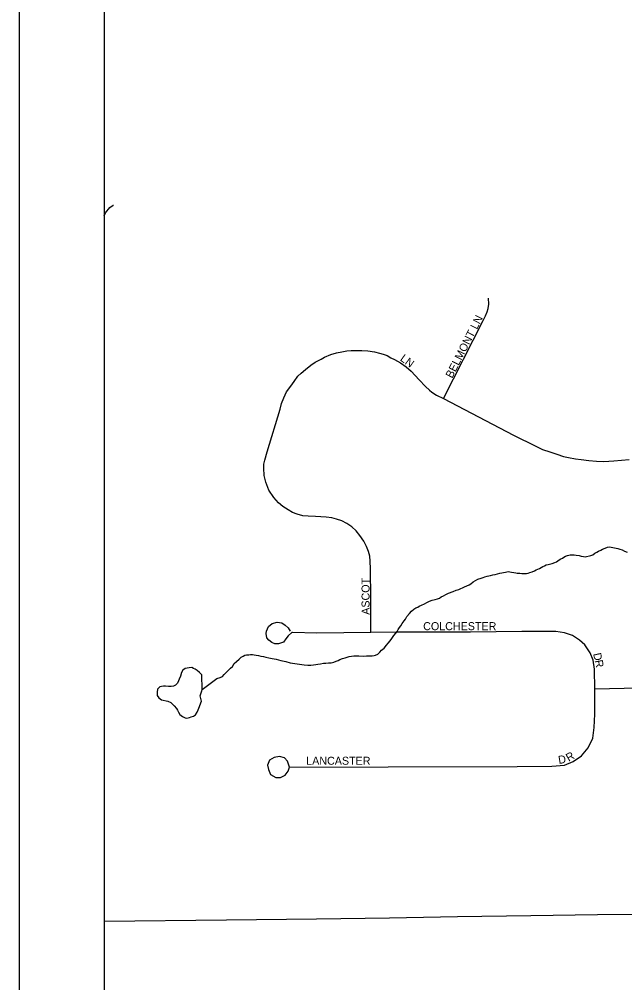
# Model space of a CAD drawing. Extents: x 0 to 34, y 0 to 22.
# Drawn here: x 2.262 to 2.978, y 16.919 to 18.059 of the extents above; entities that cross this region are included whole.
import ezdxf

# ---------------------------------------------------------------- set-up
doc = ezdxf.new("R2010")
doc.units = 0
for name, color, linetype in [('GM_X_County', 7, 'Continuous'), ('GM_X_County_Road', 7, 'Continuous'), ('GM_X_Minor_Lake', 7, 'Continuous'), ('GM_X_Minor_River', 7, 'Continuous'), ('GM_X_Township', 7, 'Continuous'), ('GM_X_Township_Subdivision', 7, 'Continuous'), ('GM_X_Township_Subdivision_Text', 7, 'Continuous'), ('SH_Data', 7, 'Continuous')]:
    doc.layers.add(name, color=color, linetype=linetype)

msp = doc.modelspace()

# ---------------------------------------------------------------- linework, layer by layer
at = {"layer": 'GM_X_County'}
msp.add_lwpolyline([(9.1622, 14.342), (9.1622, 21.1385), (2.3622, 21.1385), (2.3622, 14.3385), (9.0003, 14.3385)], dxfattribs=at)
at = {"layer": 'GM_X_County_Road'}
msp.add_lwpolyline([(2.3622, 16.9922), (2.5068, 16.9937), (2.6134, 16.9952), (2.6997, 16.9964), (2.7801, 16.9979), (2.8667, 16.9989), (2.9456, 17.0001), (3.0383, 17.0011), (3.101, 17.0021), (3.1135, 17.0021)], dxfattribs=at)
at = {"layer": 'GM_X_Minor_Lake'}
for points in [[(2.4775, 17.2835), (2.4747, 17.2865), (2.472, 17.2887), (2.4697, 17.2902), (2.4678, 17.2913), (2.4659, 17.2924), (2.4628, 17.292), (2.4579, 17.2911), (2.4553, 17.2891), (2.4534, 17.2864), (2.4524, 17.2822), (2.451, 17.2784), (2.4499, 17.2765), (2.4488, 17.2738), (2.4465, 17.2715), (2.4443, 17.2703), (2.4412, 17.2698), (2.4382, 17.2698), (2.4348, 17.2701), (2.4325, 17.2704), (2.4298, 17.27), (2.4279, 17.2695), (2.4253, 17.2668), (2.4247, 17.263), (2.4247, 17.2592), (2.4267, 17.2566), (2.4298, 17.254)], [(2.4775, 17.2835), (2.4747, 17.2865), (2.472, 17.2887), (2.4697, 17.2902), (2.4678, 17.2913), (2.4659, 17.2924), (2.4628, 17.292), (2.4579, 17.2911), (2.4553, 17.2891), (2.4534, 17.2864), (2.4524, 17.2822), (2.451, 17.2784), (2.4499, 17.2765), (2.4488, 17.2738), (2.4465, 17.2715), (2.4443, 17.2703), (2.4412, 17.2698), (2.4382, 17.2698), (2.4348, 17.2701), (2.4325, 17.2704), (2.4298, 17.27), (2.4279, 17.2695), (2.4253, 17.2668), (2.4247, 17.263), (2.4247, 17.2592), (2.4267, 17.2566), (2.4298, 17.254), (2.4374, 17.2526), (2.4409, 17.2508), (2.4428, 17.249), (2.4448, 17.2471), (2.4475, 17.2437), (2.4487, 17.2419), (2.4499, 17.2396), (2.4518, 17.2366), (2.4549, 17.2344), (2.458, 17.2329), (2.4599, 17.2326), (2.463, 17.233), (2.4652, 17.2339), (2.4679, 17.2347), (2.4701, 17.2362), (2.4723, 17.2397), (2.4734, 17.2424), (2.4748, 17.2462), (2.4763, 17.2504), (2.4774, 17.2524), (2.4765, 17.2558), (2.4757, 17.2588), (2.4764, 17.2611), (2.4775, 17.2649), (2.4782, 17.2664), (2.4775, 17.2835)], [(2.4298, 17.254), (2.4374, 17.2526), (2.4409, 17.2508), (2.4428, 17.249), (2.4448, 17.2471), (2.4475, 17.2437), (2.4487, 17.2419), (2.4499, 17.2396), (2.4518, 17.2366), (2.4549, 17.2344), (2.458, 17.2329), (2.4599, 17.2326), (2.463, 17.233), (2.4652, 17.2339), (2.4679, 17.2347), (2.4701, 17.2362), (2.4723, 17.2397), (2.4734, 17.2424), (2.4748, 17.2462), (2.4763, 17.2504), (2.4774, 17.2524), (2.4765, 17.2558), (2.4757, 17.2588), (2.4764, 17.2611), (2.4775, 17.2649), (2.4782, 17.2664), (2.4775, 17.2835)]]:
    msp.add_lwpolyline(points, dxfattribs=at)
at = {"layer": 'GM_X_Minor_River'}
for points in [[(2.3622, 17.8265), (2.3639, 17.8302), (2.3687, 17.8364), (2.3728, 17.8391), (2.3732, 17.8392)], [(2.7785, 17.3839), (2.7815, 17.3848), (2.7838, 17.3856), (2.7861, 17.3864), (2.7883, 17.3876), (2.791, 17.3888), (2.7936, 17.39), (2.7959, 17.3915), (2.7985, 17.3935), (2.8011, 17.3951), (2.8041, 17.3967), (2.8079, 17.3979), (2.8102, 17.3987), (2.8124, 17.3995), (2.8151, 17.4003), (2.817, 17.4007), (2.8189, 17.4012), (2.8219, 17.402), (2.8245, 17.4024), (2.8302, 17.4041), (2.8325, 17.4045), (2.8344, 17.4049), (2.8366, 17.4053), (2.8401, 17.4058), (2.842, 17.4055), (2.8439, 17.4051), (2.8465, 17.4048), (2.8488, 17.4045), (2.8507, 17.4041), (2.8538, 17.4038), (2.8561, 17.4035), (2.8587, 17.4035), (2.8614, 17.4036), (2.8637, 17.404), (2.8656, 17.4048), (2.8682, 17.4056), (2.8709, 17.4065), (2.8731, 17.4077), (2.8769, 17.4096), (2.8791, 17.4108), (2.881, 17.412), (2.8829, 17.4128), (2.8848, 17.4136), (2.8871, 17.414), (2.8889, 17.4145), (2.892, 17.4153), (2.895, 17.4165), (2.8969, 17.4173), (2.9002, 17.4196), (2.9021, 17.4208), (2.904, 17.4216), (2.9059, 17.4228), (2.9078, 17.424), (2.91, 17.4248), (2.9134, 17.4256), (2.9157, 17.4257), (2.918, 17.4257), (2.9203, 17.4254), (2.9237, 17.4247), (2.9264, 17.424), (2.9291, 17.4237), (2.931, 17.4233), (2.9378, 17.425), (2.9401, 17.4258), (2.9423, 17.4274), (2.9449, 17.4286), (2.9468, 17.4298), (2.9495, 17.431), (2.9513, 17.4322), (2.9547, 17.4337), (2.9574, 17.4346), (2.9593, 17.435), (2.9616, 17.4347), (2.9635, 17.4343), (2.9658, 17.434), (2.9696, 17.4333), (2.9719, 17.4322), (2.9746, 17.4315), (2.9776, 17.4301), (2.9807, 17.4286)], [(2.4782, 17.2664), (2.4954, 17.2794), (2.4992, 17.2806), (2.5019, 17.2818), (2.5041, 17.2841), (2.506, 17.286), (2.5093, 17.2892), (2.5115, 17.2915), (2.5138, 17.2934), (2.516, 17.2969), (2.5186, 17.2996), (2.5216, 17.3023), (2.5242, 17.3047), (2.5265, 17.3059), (2.5283, 17.3071), (2.5306, 17.3075), (2.5333, 17.3075), (2.5352, 17.3076), (2.5374, 17.3076), (2.5394, 17.3073), (2.542, 17.307), (2.5447, 17.3067), (2.5474, 17.3059), (2.5504, 17.3053), (2.5535, 17.3046), (2.5569, 17.3039), (2.5608, 17.3028), (2.5657, 17.3022), (2.5711, 17.3008), (2.5768, 17.2994), (2.5822, 17.298), (2.5986, 17.2953), (2.6031, 17.295), (2.6066, 17.2951), (2.6096, 17.2955), (2.6123, 17.296), (2.6149, 17.2964), (2.6179, 17.2968), (2.6214, 17.2973), (2.6244, 17.2974), (2.6274, 17.2978), (2.6305, 17.2979), (2.6339, 17.2987), (2.6365, 17.2999), (2.6388, 17.3007), (2.641, 17.3019), (2.6441, 17.3031), (2.6471, 17.3036), (2.6494, 17.3044), (2.652, 17.3052), (2.6547, 17.3056), (2.6573, 17.3061), (2.66, 17.3061), (2.6634, 17.3062), (2.6687, 17.3059), (2.6725, 17.306), (2.6759, 17.3061), (2.679, 17.3061), (2.6813, 17.3066), (2.6832, 17.307), (2.6858, 17.3082), (2.688, 17.3105), (2.6903, 17.3129), (2.6932, 17.3152), (2.6962, 17.3187), (2.6981, 17.321), (2.7003, 17.3237), (2.7025, 17.3268), (2.7047, 17.3303), (2.7069, 17.333), (2.7088, 17.3349), (2.7099, 17.3372), (2.7114, 17.3395), (2.7128, 17.3418), (2.7147, 17.3442), (2.7169, 17.3476), (2.7184, 17.3496), (2.7202, 17.3526), (2.7232, 17.3561), (2.7254, 17.3588), (2.7284, 17.3612), (2.7307, 17.3628), (2.7329, 17.3636), (2.7348, 17.3647), (2.7374, 17.3659), (2.7408, 17.3675), (2.7438, 17.3691), (2.7468, 17.3707), (2.7502, 17.3719), (2.7536, 17.3728), (2.7563, 17.3736), (2.7586, 17.3744), (2.7608, 17.3759), (2.7634, 17.3771), (2.7661, 17.3787), (2.7695, 17.3803), (2.7747, 17.3823), (2.7785, 17.3839)]]:
    msp.add_lwpolyline(points, dxfattribs=at)
at = {"layer": 'GM_X_Township'}
msp.add_lwpolyline([(2.3622, 19.6335), (2.3622, 14.3385), (4.4492, 14.3385)], dxfattribs=at)
at = {"layer": 'GM_X_Township_Subdivision'}
for points in [[(2.7633, 17.6104), (2.8104, 17.7027), (2.8131, 17.7084), (2.8152, 17.7132), (2.8164, 17.717), (2.8171, 17.7222), (2.8165, 17.7291)], [(2.6774, 17.3338), (2.6774, 17.3741), (2.677, 17.4089), (2.6769, 17.4183), (2.6762, 17.424), (2.6748, 17.4295), (2.6724, 17.4355), (2.6693, 17.4416), (2.6646, 17.4483), (2.66, 17.454), (2.655, 17.4588), (2.6493, 17.4626), (2.6431, 17.4657), (2.637, 17.4678), (2.6312, 17.4693), (2.6246, 17.4702), (2.6122, 17.4709), (2.6032, 17.4714), (2.5972, 17.4719), (2.5903, 17.4738), (2.5848, 17.4757), (2.5798, 17.4788), (2.5734, 17.4828), (2.5684, 17.4871), (2.5627, 17.4933), (2.5568, 17.5023), (2.5532, 17.5114), (2.5515, 17.5195), (2.5508, 17.5283), (2.551, 17.5328), (2.5522, 17.5376), (2.5549, 17.5476), (2.5701, 17.5978), (2.5717, 17.6047), (2.5748, 17.6113), (2.5779, 17.6185), (2.5827, 17.6251), (2.5867, 17.6306), (2.5913, 17.6368), (2.5953, 17.6406), (2.6001, 17.6447), (2.6065, 17.6499), (2.6117, 17.6537), (2.6186, 17.657), (2.6229, 17.6594), (2.6303, 17.6625), (2.637, 17.6644), (2.6431, 17.6658), (2.6491, 17.6668), (2.6543, 17.6673), (2.6603, 17.6675), (2.6667, 17.6673), (2.6738, 17.6668), (2.6819, 17.6658), (2.6879, 17.6642), (2.6922, 17.663), (2.6967, 17.6613), (2.701, 17.6587), (2.7053, 17.6568), (2.7124, 17.6527), (2.7193, 17.648), (2.7253, 17.643), (2.7345, 17.6328), (2.7422, 17.6247), (2.7467, 17.6206), (2.7498, 17.618), (2.755, 17.6144), (2.7633, 17.6104), (2.8464, 17.5671), (2.8728, 17.554), (2.8804, 17.5502), (2.8892, 17.5473), (2.8973, 17.5445), (2.9054, 17.5421), (2.9114, 17.5407), (2.9197, 17.5392), (2.9264, 17.5383), (2.9354, 17.5371), (2.9442, 17.5364), (2.953, 17.5361), (2.9647, 17.5368), (2.983, 17.5383)], [(2.5847, 17.3336), (2.5841, 17.3336), (2.5796, 17.3297), (2.577, 17.3261), (2.5741, 17.3224), (2.5684, 17.3202), (2.564, 17.3204), (2.5604, 17.3221), (2.5569, 17.3245), (2.5547, 17.3274), (2.5538, 17.3324), (2.554, 17.3352), (2.5566, 17.3408), (2.5607, 17.3445), (2.5669, 17.346), (2.5722, 17.345), (2.5762, 17.3424), (2.5798, 17.3391), (2.5822, 17.3355)], [(2.9423, 17.2667), (2.9421, 17.2903), (2.9406, 17.301), (2.9368, 17.3098), (2.9306, 17.3191), (2.9241, 17.3246), (2.9161, 17.33), (2.9066, 17.3334), (2.8964, 17.335), (2.8559, 17.3348), (2.7955, 17.3343), (2.7079, 17.3341), (2.6774, 17.3338), (2.6138, 17.3331), (2.5847, 17.3336)], [(2.5813, 17.1746), (2.5791, 17.1815), (2.5753, 17.1856), (2.5694, 17.187), (2.5632, 17.186), (2.5577, 17.1827), (2.5553, 17.1768), (2.5563, 17.1718), (2.5589, 17.1658), (2.5651, 17.1622), (2.5708, 17.1622), (2.5763, 17.1649), (2.5798, 17.1696), (2.5813, 17.1746), (2.6979, 17.1749), (2.8504, 17.1753), (2.8916, 17.1756), (2.9064, 17.1768), (2.9168, 17.1813), (2.9268, 17.1877), (2.9347, 17.1972), (2.9402, 17.2089), (2.9418, 17.2215), (2.9423, 17.237), (2.9423, 17.2667)], [(3.1413, 17.2534), (3.1312, 17.2556), (3.1177, 17.2605), (3.1075, 17.2647), (3.0989, 17.2677), (3.092, 17.2691), (3.0787, 17.2693), (3.0289, 17.2685), (2.9423, 17.2667)]]:
    msp.add_lwpolyline(points, dxfattribs=at)
at = {"layer": 'SH_Data'}
msp.add_line((2.2617, 21.2383), (2.2617, 14.2383), dxfattribs=at)

# ---------------------------------------------------------------- texts
at = {"layer": 'GM_X_Township_Subdivision_Text'}
for s, rotation, p in [('BELMONT LN', 63.1446, (2.7737, 17.6338)), ('LN', 323.7481, (2.7113, 17.6561)), ('ASCOT', 90, (2.676, 17.3547)), ('COLCHESTER', 0, (2.7394, 17.3365)), ('D', 282.9864, (2.9403, 17.3085)), ('R', 280.8241, (2.9422, 17.3005)), ('LANCASTER', 0, (2.6011, 17.1773)), ('D', 9.3509, (2.8999, 17.1782)), ('R', 29.7349, (2.9115, 17.1807))]:
    msp.add_text(s, height=0.00947, rotation=rotation, dxfattribs=at).set_placement(p)

doc.saveas('drawing.dxf')
